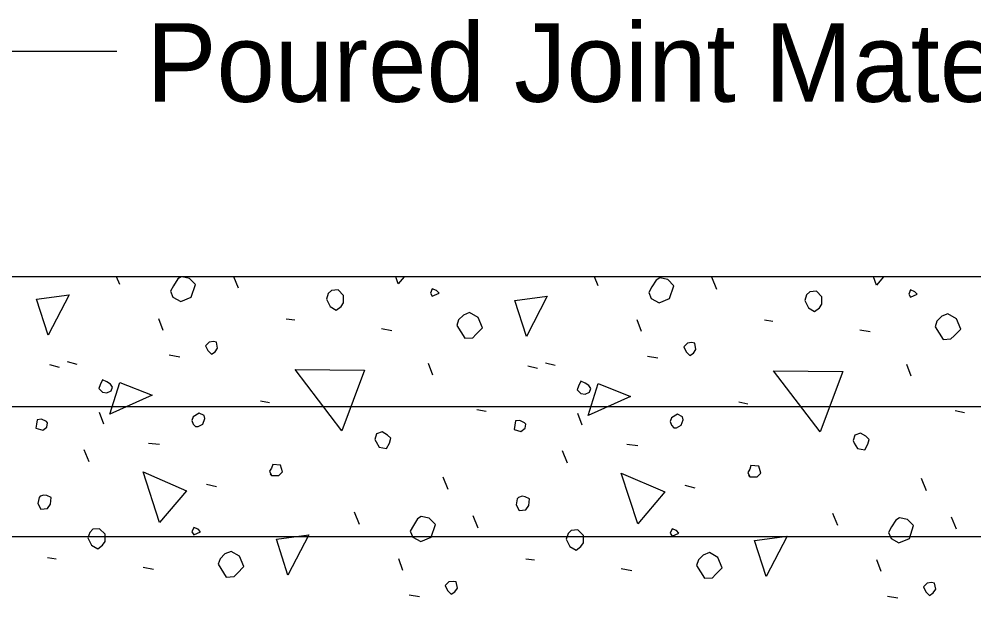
# Model space of a CAD drawing. Extents: x 0 to 15.4, y 0 to 9.7.
# Drawn here: x 4.08 to 5, y 3.723 to 4.28 of the extents above; entities that cross this region are included whole.
import ezdxf

# ---------------------------------------------------------------- set-up
doc = ezdxf.new("R2010")
doc.units = 0
for name, color, linetype in [('Dimension', 7, 'Continuous'), ('Miscellaneous', 7, 'Continuous'), ('SupstrConc', 7, 'Continuous'), ('TextStructures', 7, 'Continuous')]:
    doc.layers.add(name, color=color, linetype=linetype)

msp = doc.modelspace()

# ---------------------------------------------------------------- linework, layer by layer
at = {"layer": 'Dimension'}
for p, q in [((4.06524, 3.9072), (6.06087, 3.9072)), ((3.88153, 3.7822), (6.06087, 3.7822))]:
    msp.add_line(p, q, dxfattribs=at)
msp.add_open_spline([(4.17372, 4.24889), (4.11296, 4.24889), (4.02182, 4.24889), (3.90219, 4.16341), (3.81864, 4.02095), (3.74859, 3.90721)], degree=2, dxfattribs=at)
at = {"layer": 'Miscellaneous'}
for p, q in [((4.17662, 4.02473), (4.17362, 4.03223)), ((4.29093, 4.0212), (4.28652, 4.03223)), ((4.63741, 4.02355), (4.63394, 4.03223)), ((4.75173, 4.02002), (4.74702, 4.0318)), ((4.21845, 3.98054), (4.21433, 3.99173)), ((4.33689, 3.99173), (4.34514, 3.99056)), ((4.67925, 3.97936), (4.67513, 3.99056)), ((4.79769, 3.99056), (4.80594, 3.98938)), ((4.42882, 3.98231), (4.43884, 3.98054)), ((4.88962, 3.98113), (4.89963, 3.97936)), ((4.22435, 3.95697), (4.23436, 3.9552)), ((4.68514, 3.95579), (4.69516, 3.95402)), ((4.10885, 3.94754), (4.11828, 3.94518)), ((4.12594, 3.95049), (4.13537, 3.94813)), ((4.47832, 3.93752), (4.47419, 3.94872)), ((4.56965, 3.94636), (4.57908, 3.944)), ((4.58674, 3.94931), (4.59617, 3.94695)), ((4.93911, 3.93634), (4.93499, 3.94754)), ((4.31215, 3.91277), (4.32098, 3.91101)), ((4.77294, 3.9116), (4.78178, 3.90983)), ((4.1613, 3.89038), (4.15717, 3.90158)), ((4.52074, 3.90452), (4.52958, 3.90276)), ((4.62209, 3.8892), (4.61797, 3.9004)), ((4.98154, 3.90335), (4.99038, 3.90158)), ((4.14715, 3.85385), (4.14244, 3.86563)), ((4.20431, 3.87211), (4.21492, 3.87094)), ((4.60795, 3.85267), (4.60324, 3.86445)), ((4.66511, 3.87094), (4.67572, 3.86976)), ((4.49305, 3.82733), (4.48833, 3.83912)), ((4.95385, 3.82615), (4.94913, 3.83794)), ((4.26029, 3.83263), (4.26972, 3.83028)), ((4.72109, 3.83146), (4.73052, 3.8291)), ((4.40761, 3.79374), (4.40289, 3.80553)), ((4.52192, 3.79021), (4.51721, 3.80199)), ((4.8684, 3.79257), (4.86369, 3.80435)), ((4.98272, 3.78903), (4.978, 3.80081)), ((4.10708, 3.76192), (4.11533, 3.76075)), ((4.44944, 3.74955), (4.44532, 3.76075)), ((4.56788, 3.76075), (4.57613, 3.75957)), ((4.91024, 3.74837), (4.90612, 3.75957)), ((4.19901, 3.7525), (4.20903, 3.75073)), ((4.65981, 3.75132), (4.66982, 3.74955)), ((4.45533, 3.72598), (4.46535, 3.72421)), ((4.91613, 3.7248), (4.92615, 3.72303))]:
    msp.add_line(p, q, dxfattribs=at)
for points in [[(4.23589, 4.03223), (4.2326, 4.03004), (4.22847, 4.02355), (4.22553, 4.01825), (4.22788, 4.01236)], [(4.22788, 4.01236), (4.23554, 4.00823), (4.24556, 4.01236), (4.24968, 4.02473), (4.24379, 4.03062), (4.23682, 4.03223)], [(4.44473, 4.02532), (4.44248, 4.03223)], [(4.45058, 4.03223), (4.44473, 4.02532)], [(4.68868, 4.01118), (4.69634, 4.00705), (4.70636, 4.01118), (4.71048, 4.02355), (4.70459, 4.02945), (4.69693, 4.03121), (4.69339, 4.02886), (4.68927, 4.02238), (4.68632, 4.01707), (4.68868, 4.01118)], [(4.90553, 4.02414), (4.90289, 4.03223)], [(4.91237, 4.03223), (4.90553, 4.02414)], [(4.47773, 4.01354), (4.48421, 4.01648), (4.48185, 4.01884), (4.47773, 4.02061), (4.47596, 4.01648), (4.47773, 4.01354)], [(4.10767, 3.97582), (4.09648, 4.01059), (4.12771, 4.01471), (4.10767, 3.97582)], [(4.37579, 4.01059), (4.37932, 4.00352), (4.38521, 3.99998), (4.38993, 4.00352), (4.39228, 4.00705), (4.39228, 4.01413), (4.38698, 4.01943), (4.3805, 4.01884), (4.37755, 4.01589), (4.37579, 4.01059)], [(4.56847, 3.97465), (4.55728, 4.00941), (4.58851, 4.01354), (4.56847, 3.97465)], [(4.83658, 4.00941), (4.84012, 4.00234), (4.84601, 3.9988), (4.85073, 4.00234), (4.85308, 4.00588), (4.85308, 4.01295), (4.84778, 4.01825), (4.8413, 4.01766), (4.83835, 4.01471), (4.83658, 4.00941)], [(4.93852, 4.01236), (4.94501, 4.0153), (4.94265, 4.01766), (4.93852, 4.01943), (4.93676, 4.0153), (4.93852, 4.01236)], [(4.5013, 3.98525), (4.50896, 3.97288), (4.51662, 3.97347), (4.51956, 3.97641), (4.52605, 3.98289), (4.52192, 3.99291), (4.51367, 3.99763), (4.50778, 3.99527), (4.50306, 3.99056), (4.5013, 3.98525)], [(4.96209, 3.98407), (4.96976, 3.9717), (4.97742, 3.97229), (4.98036, 3.97523), (4.98684, 3.98172), (4.98272, 3.99173), (4.97447, 3.99645), (4.96858, 3.99409), (4.96386, 3.98938), (4.96209, 3.98407)], [(4.26147, 3.96109), (4.26501, 3.95756), (4.26854, 3.95991), (4.2709, 3.96345), (4.26972, 3.96934), (4.26677, 3.96993), (4.26265, 3.96934), (4.25911, 3.96581), (4.26147, 3.96109)], [(4.72227, 3.95991), (4.7258, 3.95638), (4.72934, 3.95874), (4.7317, 3.96227), (4.73052, 3.96816), (4.72757, 3.96875), (4.72345, 3.96816), (4.71991, 3.96463), (4.72227, 3.95991)], [(4.39052, 3.8839), (4.34573, 3.94283), (4.41232, 3.94224), (4.39052, 3.8839)], [(4.85131, 3.88272), (4.80653, 3.94165), (4.87312, 3.94106), (4.85131, 3.88272)], [(4.16012, 3.92102), (4.16424, 3.92043), (4.16837, 3.9222), (4.16955, 3.92574), (4.16778, 3.92868), (4.16424, 3.93104), (4.16012, 3.93281), (4.15776, 3.92809), (4.15658, 3.92456), (4.16012, 3.92102)], [(4.16719, 3.89981), (4.17662, 3.93045), (4.20785, 3.91808), (4.16719, 3.89981)], [(4.62092, 3.91984), (4.62504, 3.91926), (4.62917, 3.92102), (4.63034, 3.92456), (4.62858, 3.9275), (4.62504, 3.92986), (4.62092, 3.93163), (4.61856, 3.92692), (4.61738, 3.92338), (4.62092, 3.91984)], [(4.62799, 3.89863), (4.63741, 3.92927), (4.66865, 3.9169), (4.62799, 3.89863)], [(4.24968, 3.88802), (4.25204, 3.88802), (4.25676, 3.89038), (4.25852, 3.89569), (4.25793, 3.89863), (4.25322, 3.90099), (4.24733, 3.89745), (4.24615, 3.89392), (4.24733, 3.89038), (4.24968, 3.88802)], [(4.09589, 3.88626), (4.10237, 3.88449), (4.1065, 3.88744), (4.10708, 3.89156), (4.10591, 3.89274), (4.10119, 3.8951), (4.09707, 3.89451), (4.09648, 3.89038), (4.09589, 3.88626)], [(4.55669, 3.88508), (4.56317, 3.88331), (4.56729, 3.88626), (4.56788, 3.89038), (4.5667, 3.89156), (4.56199, 3.89392), (4.55787, 3.89333), (4.55728, 3.8892), (4.55669, 3.88508)], [(4.71048, 3.88685), (4.71284, 3.88685), (4.71755, 3.8892), (4.71932, 3.89451), (4.71873, 3.89745), (4.71402, 3.89981), (4.70813, 3.89627), (4.70695, 3.89274), (4.70813, 3.8892), (4.71048, 3.88685)], [(4.42352, 3.87329), (4.42646, 3.86799), (4.43353, 3.86681), (4.43648, 3.87211), (4.43766, 3.87683), (4.43471, 3.87978), (4.42941, 3.88272), (4.4241, 3.88095), (4.42234, 3.87565), (4.42352, 3.87329)], [(4.88431, 3.87211), (4.88726, 3.86681), (4.89433, 3.86563), (4.89728, 3.87094), (4.89846, 3.87565), (4.89551, 3.8786), (4.89021, 3.88154), (4.8849, 3.87978), (4.88313, 3.87447), (4.88431, 3.87211)], [(4.32275, 3.84088), (4.32982, 3.84088), (4.33336, 3.84442), (4.33159, 3.8509), (4.32393, 3.85149), (4.32275, 3.84796), (4.32098, 3.84501), (4.32275, 3.84088), (4.32157, 3.84206)], [(4.78355, 3.83971), (4.79062, 3.83971), (4.79416, 3.84324), (4.79239, 3.84972), (4.78473, 3.85031), (4.78355, 3.84678), (4.78178, 3.84383), (4.78355, 3.83971), (4.78237, 3.84088)], [(4.21492, 3.79551), (4.19901, 3.84442), (4.24085, 3.82615), (4.21492, 3.79551)], [(4.67572, 3.79433), (4.65981, 3.84324), (4.70164, 3.82497), (4.67572, 3.79433)], [(4.09766, 3.81378), (4.1006, 3.80848), (4.10708, 3.80906), (4.11003, 3.81319), (4.11062, 3.81967), (4.1065, 3.82144), (4.10355, 3.82203), (4.10001, 3.82085), (4.09884, 3.81967), (4.09766, 3.81378)], [(4.55845, 3.8126), (4.5614, 3.8073), (4.56788, 3.80789), (4.57083, 3.81201), (4.57142, 3.81849), (4.56729, 3.82026), (4.56435, 3.82085), (4.56081, 3.81967), (4.55963, 3.81849), (4.55845, 3.8126)], [(4.45887, 3.78137), (4.46653, 3.77724), (4.47655, 3.78137), (4.48067, 3.79374), (4.47478, 3.79964), (4.46712, 3.8014), (4.46358, 3.79905), (4.45946, 3.79257), (4.45651, 3.78726), (4.45887, 3.78137)], [(4.91967, 3.78019), (4.92733, 3.77607), (4.93735, 3.78019), (4.94147, 3.79257), (4.93558, 3.79846), (4.92792, 3.80023), (4.92438, 3.79787), (4.92026, 3.79139), (4.91731, 3.78608), (4.91967, 3.78019)], [(4.24792, 3.78373), (4.2544, 3.78667), (4.25204, 3.78903), (4.24792, 3.7908), (4.24615, 3.78667), (4.24792, 3.78373)], [(4.14598, 3.78078), (4.14951, 3.77371), (4.1554, 3.77017), (4.16012, 3.77371), (4.16247, 3.77724), (4.16247, 3.78432), (4.15717, 3.78962), (4.15069, 3.78903), (4.14774, 3.78608), (4.14598, 3.78078)], [(4.33866, 3.74484), (4.32747, 3.7796), (4.3587, 3.78373), (4.33866, 3.74484)], [(4.60677, 3.7796), (4.61031, 3.77253), (4.6162, 3.769), (4.62092, 3.77253), (4.62327, 3.77607), (4.62327, 3.78314), (4.61797, 3.78844), (4.61149, 3.78785), (4.60854, 3.78491), (4.60677, 3.7796)], [(4.70871, 3.78255), (4.7152, 3.78549), (4.71284, 3.78785), (4.70871, 3.78962), (4.70695, 3.78549), (4.70871, 3.78255)], [(4.79946, 3.74366), (4.78826, 3.77842), (4.81949, 3.78255), (4.79946, 3.74366)], [(4.27149, 3.75544), (4.27915, 3.74307), (4.28681, 3.74366), (4.28975, 3.7466), (4.29624, 3.75309), (4.29211, 3.7631), (4.28386, 3.76782), (4.27797, 3.76546), (4.27325, 3.76075), (4.27149, 3.75544)], [(4.73229, 3.75426), (4.73995, 3.74189), (4.74761, 3.74248), (4.75055, 3.74542), (4.75703, 3.75191), (4.75291, 3.76192), (4.74466, 3.76664), (4.73877, 3.76428), (4.73405, 3.75957), (4.73229, 3.75426)], [(4.49246, 3.7301), (4.49599, 3.72657), (4.49953, 3.72893), (4.50189, 3.73246), (4.50071, 3.73835), (4.49776, 3.73894), (4.49364, 3.73835), (4.4901, 3.73482), (4.49246, 3.7301)], [(4.95326, 3.72893), (4.95679, 3.72539), (4.96033, 3.72775), (4.96268, 3.73128), (4.96151, 3.73718), (4.95856, 3.73776), (4.95443, 3.73718), (4.9509, 3.73364), (4.95326, 3.72893)]]:
    msp.add_lwpolyline(points, dxfattribs=at)
at = {"layer": 'SupstrConc'}
msp.add_line((5.44087, 4.0322), (4.06097, 4.0322), dxfattribs=at)

# ---------------------------------------------------------------- texts
at = {"layer": 'TextStructures'}
msp.add_text('Poured Joint Material', height=0.0756002, dxfattribs=at).set_placement((4.20241, 4.20053))

doc.saveas('drawing.dxf')
